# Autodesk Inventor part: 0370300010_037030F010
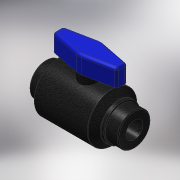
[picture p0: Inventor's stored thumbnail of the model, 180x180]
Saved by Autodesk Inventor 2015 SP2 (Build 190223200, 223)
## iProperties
Created: 2017-06
Part Number: 0370300010_037030F010
Material: PVC-Piping
Description: PLASSON BALL VALVE DN25 FEMALE 1" BSPT
Document SubType Name: Modeling
Designer: KIM
Mass: 486.116 g
Surface Area: 424.519 cm^2
Volume: 347.226 cm^3
Density: 1.4 g/cm^3
Appearance: Black Cast
Author: KIM
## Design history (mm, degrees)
derived "03703.ipt"
feature "Solid1::03703.ipt"
tag "TaggingFeature1"
body "Solid1"
other parameters: "d0" = 116, "d3" = 66, "d4" = 20.5, "d5" = 30.291, "d6" = 30.291, "d7" = 20.5, "d8" = 46, "d9" = 16.4, "d10" = 50.6, "d11" = 15.0485, "d12" = 135 deg, "d14" = 1.51455, "d24" = 18.1746, "d25" = 42.9, "d27" = 18.1746, "d28" = 9.0873, "d29" = 21.1, "d30" = 0, "d32" = 39.98412, "d33" = 4.54365, "d34" = 1.51455, "Rc_" = 30.291, "A_1" = 33, "A_2" = 64, "H_" = 116, "l_" = 20.5, "B_" = 46, "E_" = 1, "d31" = 36.3492
